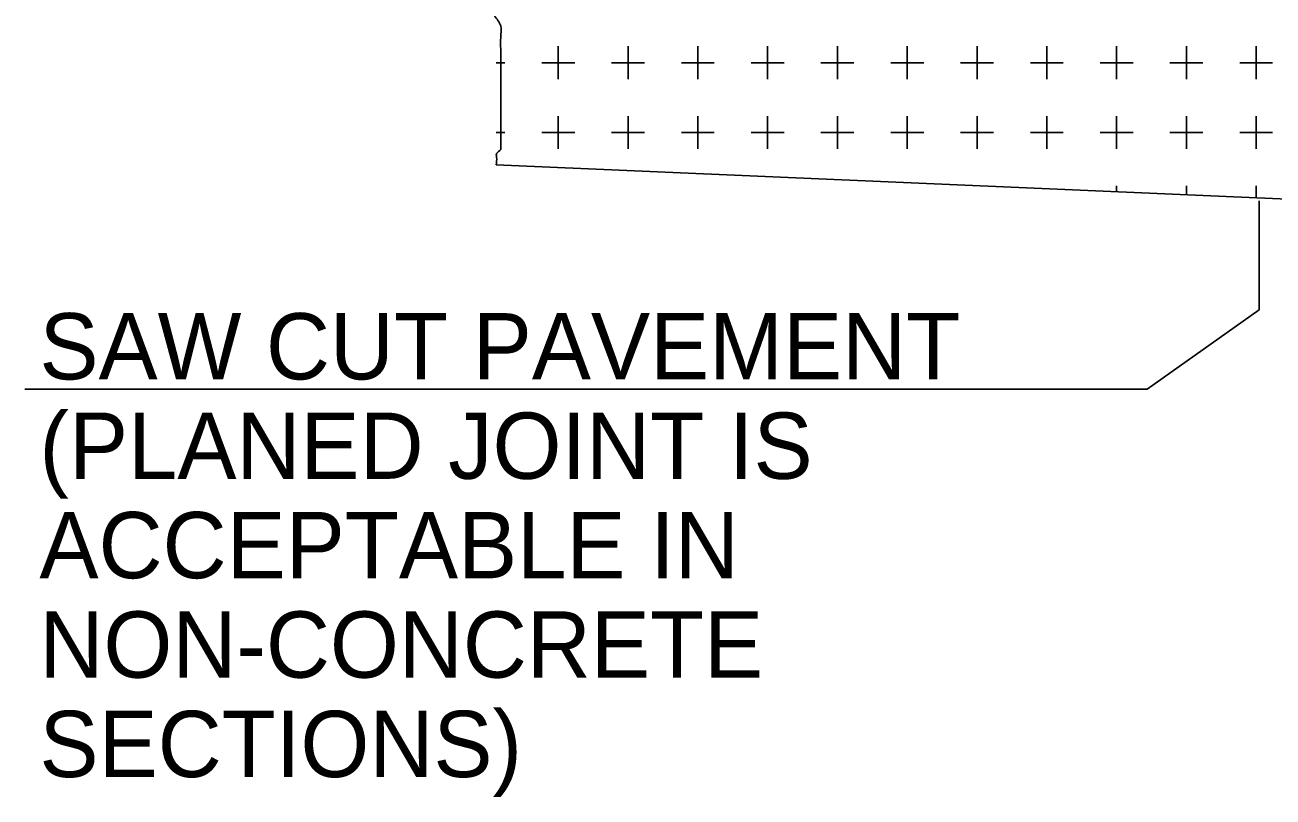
# Model space of a CAD drawing. Extents: x 0 to 34, y -1.4 to 22.
# Drawn here: x 17.49 to 20.126, y 12.543 to 14.174 of the extents above; entities that cross this region are included whole.
import ezdxf

# ---------------------------------------------------------------- set-up
doc = ezdxf.new("R2010")
doc.units = 0
doc.layers.add('SH_Text', color=7, linetype='Continuous')

msp = doc.modelspace()

# ---------------------------------------------------------------- linework, layer by layer
at = {"layer": 'SH_Text'}
for p, q in [((18.6163, 14.0937), (18.6163, 14.1286)), ((18.7637, 14.0591), (18.7637, 14.1286)), ((18.9112, 14.0937), (18.9112, 14.1286)), ((19.0585, 14.0591), (19.0585, 14.1286)), ((19.206, 14.0937), (19.206, 14.1286)), ((19.3533, 14.0591), (19.3533, 14.1286)), ((19.5008, 14.0937), (19.5008, 14.1286)), ((19.6482, 14.0591), (19.6482, 14.1286)), ((19.7957, 14.0937), (19.7957, 14.1286)), ((19.943, 14.0591), (19.943, 14.1286)), ((20.0903, 14.0937), (20.0903, 14.1286)), ((18.4848, 14.0937), (18.5035, 14.0937)), ((18.5815, 14.0937), (18.6163, 14.0937)), ((18.6163, 14.0591), (18.6163, 14.0937)), ((18.6163, 14.0937), (18.651, 14.0937)), ((18.729, 14.0937), (18.7985, 14.0937)), ((18.8763, 14.0937), (18.9112, 14.0937)), ((18.9112, 14.0591), (18.9112, 14.0937)), ((18.9112, 14.0937), (18.9458, 14.0937)), ((19.0238, 14.0937), (19.0933, 14.0937)), ((19.1712, 14.0937), (19.206, 14.0937)), ((19.206, 14.0591), (19.206, 14.0937)), ((19.206, 14.0937), (19.2407, 14.0937)), ((19.3187, 14.0937), (19.3882, 14.0937)), ((19.466, 14.0937), (19.5008, 14.0937)), ((19.5008, 14.0591), (19.5008, 14.0937)), ((19.5008, 14.0937), (19.5355, 14.0937)), ((19.6135, 14.0937), (19.683, 14.0937)), ((19.7608, 14.0937), (19.7957, 14.0937)), ((19.7957, 14.0591), (19.7957, 14.0937)), ((19.7957, 14.0937), (19.8303, 14.0937)), ((19.9082, 14.0937), (19.9777, 14.0937)), ((20.0557, 14.0937), (20.0903, 14.0937)), ((20.0903, 14.0591), (20.0903, 14.0937)), ((20.0903, 14.0937), (20.1252, 14.0937)), ((18.6163, 13.9116), (18.6163, 13.9811)), ((18.7637, 13.9464), (18.7637, 13.9811)), ((18.9112, 13.9116), (18.9112, 13.9811)), ((19.0585, 13.9464), (19.0585, 13.9811)), ((19.206, 13.9116), (19.206, 13.9811)), ((19.3533, 13.9464), (19.3533, 13.9811)), ((19.5008, 13.9116), (19.5008, 13.9811)), ((19.6482, 13.9464), (19.6482, 13.9811)), ((19.7957, 13.9116), (19.7957, 13.9811)), ((19.943, 13.9464), (19.943, 13.9811)), ((20.0903, 13.9116), (20.0903, 13.9811)), ((18.4848, 13.9464), (18.5035, 13.9464)), ((18.5815, 13.9464), (18.651, 13.9464)), ((18.729, 13.9464), (18.7637, 13.9464)), ((18.7637, 13.9116), (18.7637, 13.9464)), ((18.7637, 13.9464), (18.7985, 13.9464)), ((18.8763, 13.9464), (18.9458, 13.9464)), ((19.0238, 13.9464), (19.0585, 13.9464)), ((19.0585, 13.9116), (19.0585, 13.9464)), ((19.0585, 13.9464), (19.0933, 13.9464)), ((19.1712, 13.9464), (19.2407, 13.9464)), ((19.3187, 13.9464), (19.3533, 13.9464)), ((19.3533, 13.9116), (19.3533, 13.9464)), ((19.3533, 13.9464), (19.3882, 13.9464)), ((19.466, 13.9464), (19.5355, 13.9464)), ((19.6135, 13.9464), (19.6482, 13.9464)), ((19.6482, 13.9116), (19.6482, 13.9464)), ((19.6482, 13.9464), (19.683, 13.9464)), ((19.7608, 13.9464), (19.8303, 13.9464)), ((19.9082, 13.9464), (19.943, 13.9464)), ((19.943, 13.9116), (19.943, 13.9464)), ((19.943, 13.9464), (19.9777, 13.9464)), ((20.0557, 13.9464), (20.1252, 13.9464)), ((19.7957, 13.8212), (19.7957, 13.8337)), ((19.943, 13.8149), (19.943, 13.8337)), ((20.0903, 13.8086), (20.0903, 13.8337)), ((20.0965, 13.802), (20.0965, 13.5716)), ((19.8599, 13.4041), (20.0965, 13.5716)), ((17.4898, 13.4041), (19.8599, 13.4041))]:
    msp.add_line(p, q, dxfattribs=at)
msp.add_lwpolyline([(18.4848, 13.8781), (20.8388, 13.7761), (20.8573, 13.7737)], dxfattribs=at)
msp.add_spline([(18.4848, 15.0926), (18.4795, 15.0766), (18.4903, 15.0646), (18.4903, 15.0524), (18.4903, 15.0484), (18.4903, 15.0362), (18.4903, 15.0241), (18.4838, 14.9856), (18.4838, 14.9694), (18.4903, 14.9532), (18.4903, 14.9451), (18.4903, 14.9411), (18.4903, 14.9329), (18.4903, 14.9227), (18.4903, 14.9187), (18.4848, 14.9047), (18.499, 14.8864), (18.499, 14.8702), (18.499, 14.8661), (18.4925, 14.8539), (18.4925, 14.8459), (18.4925, 14.8337), (18.4925, 14.8156), (18.4925, 14.8034), (18.4925, 14.7851), (18.486, 14.7629), (18.486, 14.7182), (18.486, 14.7021), (18.486, 14.6697), (18.486, 14.6414), (18.486, 14.6191), (18.486, 14.6069), (18.486, 14.5807), (18.486, 14.5766), (18.486, 14.5644), (18.486, 14.5482), (18.486, 14.5301), (18.486, 14.5219), (18.486, 14.4996), (18.486, 14.4754), (18.486, 14.4511), (18.4903, 14.4369), (18.4903, 14.4287), (18.4903, 14.4207), (18.4903, 14.4004), (18.4903, 14.3922), (18.4903, 14.3842), (18.4838, 14.3701), (18.4775, 14.3377), (18.4775, 14.3296), (18.4775, 14.3114), (18.4775, 14.3032), (18.4775, 14.2911), (18.4775, 14.2729), (18.4775, 14.2607), (18.4775, 14.2426), (18.4775, 14.2222), (18.4775, 14.2101), (18.4817, 14.1939), (18.4947, 14.1716), (18.4947, 14.1474), (18.4947, 14.1231), (18.4947, 14.1027), (18.4947, 14.0664), (18.4947, 14.0299), (18.4947, 14.0077), (18.4947, 13.9814), (18.4947, 13.9631), (18.4947, 13.9449), (18.4947, 13.9409), (18.4947, 13.9226), (18.4947, 13.9186), (18.4947, 13.9104), (18.486, 13.9024), (18.486, 13.8942), (18.4848, 13.8781)], degree=3, dxfattribs=at)

# ---------------------------------------------------------------- texts
for s, p in [('SAW CUT PAVEMENT', (17.5204, 13.4249)), ('(PLANED JOINT IS', (17.5204, 13.2149)), ('ACCEPTABLE IN', (17.5204, 13.0049)), ('NON-CONCRETE', (17.5204, 12.7949)), ('SECTIONS)', (17.5204, 12.5849))]:
    msp.add_text(s, height=0.14, dxfattribs=at).set_placement(p)

doc.saveas('drawing.dxf')
